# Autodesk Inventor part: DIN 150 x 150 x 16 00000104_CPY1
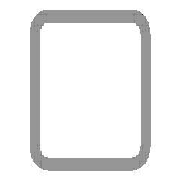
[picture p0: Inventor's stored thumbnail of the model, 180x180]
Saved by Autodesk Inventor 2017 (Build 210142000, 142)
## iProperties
Created: 2017-11
Part Number: DIN 150 x 150 x 16 00000104_CPY1
Material: Steel, Mild
Description: Cold formed welded structural hollow sections of non-alloy and fine grain structural steel
Document SubType Name: Modeling
Standard: DIN
Designer: iusti
Standard Revision: 2006-07
Standards Organization: DIN
Language: en-US
Size Designation: 150 x 150 x 16
Categories: <MemberInstance><Categories><Category DisplayName="Structural Shapes" InternalName="089c4875-fa83-4c05-b084-43b9cc11f5ed" Mnemonic="GRDR"><CategoryParameter Dis
Stock Number: 150 x 150 x 16
Mass: 301820 g
Surface Area: 48238.1 cm^2
Volume: 38448.4 cm^3
Density: 7.85 g/cm^3
Appearance: Semi-Polished
IsCustomPart: 1
G_W: 150.000 mm
G_H: 150.000 mm
G_L: 5233.011 mm
+29768780-A419-4CF3-9340-1BC278E7B28F+CUTDETAIL2: Cut
+346FD258-9F9C-4BDE-884E-4FE9BE76FCEA+CUTDETAIL3: Miter 69.88 deg
_CCFamilyMember: 76
_CCFamilyDisplayName: DIN EN 10219-2 (Square Hollow Section - Cold Formed) - Cold formed welded structural hollow sections of non-alloy and fine grain structural steel
_FrameMemberDoc: Frame Member File
_Version: 15.0.0
_GetPNFromCC: 1
Author: iusti
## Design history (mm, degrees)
node "Start plane"
node "End plane"
sketch "Sketch"
  geometry: L1 (-75, -27)-(-75, 27); L2 (-27, 75)-(27, 75); L3 (75, 27)-(75, -27); L4 (27, -75)-(-27, -75); L5 (-27, 59)-(27, 59); L6 (59, 27)-(59, -27); L7 (27, -59)-(-27, -59); L8 (-59, -27)-(-59, 27); L9 (0, 118.918)-(0, -118.918) reference; L10 (-118.918, 0)-(118.918, 0) reference; A1 r 48 centre (-27, -27) between (-75, -27) and (-27, -75); A2 r 48 centre (-27, 27) between (-27, 75) and (-75, 27); A3 r 48 centre (27, 27) between (75, 27) and (27, 75); A4 r 48 centre (27, -27) between (27, -75) and (75, -27); A5 r 32 centre (-27, 27) between (-27, 59) and (-59, 27); A6 r 32 centre (27, 27) between (59, 27) and (27, 59); A7 r 32 centre (27, -27) between (27, -59) and (59, -27); A8 r 32 centre (-27, -27) between (-59, -27) and (-27, -59)
  constraints: 16 end point, 16 point on circle, 8 centre point, 8 tangent, 4 parallel, 3 equal radius, 2 perpendicular, 7 other
  dimensions: "d7" = 48 radius of A1 (= G_IR); "d10" = 150 distance between parallel lines of L2 L4 (= G_H); "d11" = 150 distance between parallel lines of L1 L3 (= G_W); "d12" = 16 distance between parallel lines of L3 L6 (= G_T); "d15" = 75 distance between parallel lines of L2 L10 (= 0.5 x d10); "d16" = 75 distance between parallel lines of L9 L3 (= 0.5 x d11)
extrude "Body" new body sketch "Sketch" stored distance "d3" = 5233.01077 (= G_L); taper "d4" = 0 deg
node "Driven Length"
  sketch "Sketch3"
    geometry: L1 (0, 0)-(10, 0) reference
    constraints: 2 end point, 1 horizontal
  workplane "Work Plane3"
  sketch "Sketch4"
    geometry: L1 (-2, 34.78)-(12, 34.78) reference; L2 (-2, 5267.791)-(12, 5267.791) reference
    dimensions: "d18" = 5233.01077 distance between parallel lines of L1 L2 (derived)
workplane "Work Plane5"
split "Split2"
workplane "Work Plane6"
split "Split3"
body "Solid1"
other parameters: "G_W" = 150 [user parameter; used in 1 equation term], "G_H" = 150 [user parameter; used in 1 equation term], "G_T" = 16 [user parameter; used in 1 equation term], "G_IR" = 48 [user parameter; used in 1 equation term], "G_L" = 5233.01077 (= d18) [user parameter; used in 1 equation term], "G_OFFSET_START" = -34.77977 [user parameter; used in 1 equation term], "G_OFFSET_END" = 27.4779 [user parameter; used in 1 equation term], "d13" = 34.77977 (= -G_OFFSET_START), "d14" = 5267.79054 (= G_OFFSET_END + B_L), "B_L" = 5240.31264 [user parameter; used in 1 equation term], "d17" = 90 deg
